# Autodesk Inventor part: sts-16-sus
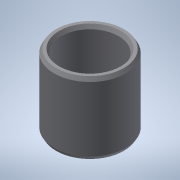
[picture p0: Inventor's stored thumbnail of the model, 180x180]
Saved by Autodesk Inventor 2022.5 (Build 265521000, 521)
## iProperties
Created: 2016-12
Part Number: sts-16-sus
Material: 一般
Document SubType Name: Modeling
Designer: imaocorp
Density: 1 g/cm^3
Appearance: 既定
Author: imaocorp
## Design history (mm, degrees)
node "sts-16-sus.x_t1"
node "sts-16-sus"
node "Base1"
